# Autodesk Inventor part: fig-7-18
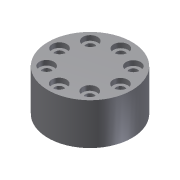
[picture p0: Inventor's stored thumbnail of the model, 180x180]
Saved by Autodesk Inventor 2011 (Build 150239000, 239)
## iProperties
Created: 2004-05
Part Number: fig-7-18
Document SubType Name: Modeling
Designer: CADCIM Technologies
Manufacturer: Standard
Standards Organization: Custom
Density: 1 g/cm^3
Author: CADCIM Technologies
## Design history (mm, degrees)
sketch "Sketch1"
  geometry: C1 r 17.175 at (0, 0)
  constraints: 1 centre point
extrude "Extrusion1" new body sketch "Sketch1" distance "d0" = 17; taper "d1" = 0 deg
sketch "Sketch2"
  geometry: 1 further point
hole "Hole1" sketch "Sketch2" at (12.571, -0.074) diameter "d2" = 3.5; stored, may be unused: countersink angle "d6" = 90 deg, drill point angle "d8" = 118 deg; dims "d3" = 6, "d4" = 6, "d5" = 2, "d7" = 8
pattern_circular "Circular Pattern1" dims angle "d11" = 360 deg
body "Solid1"
